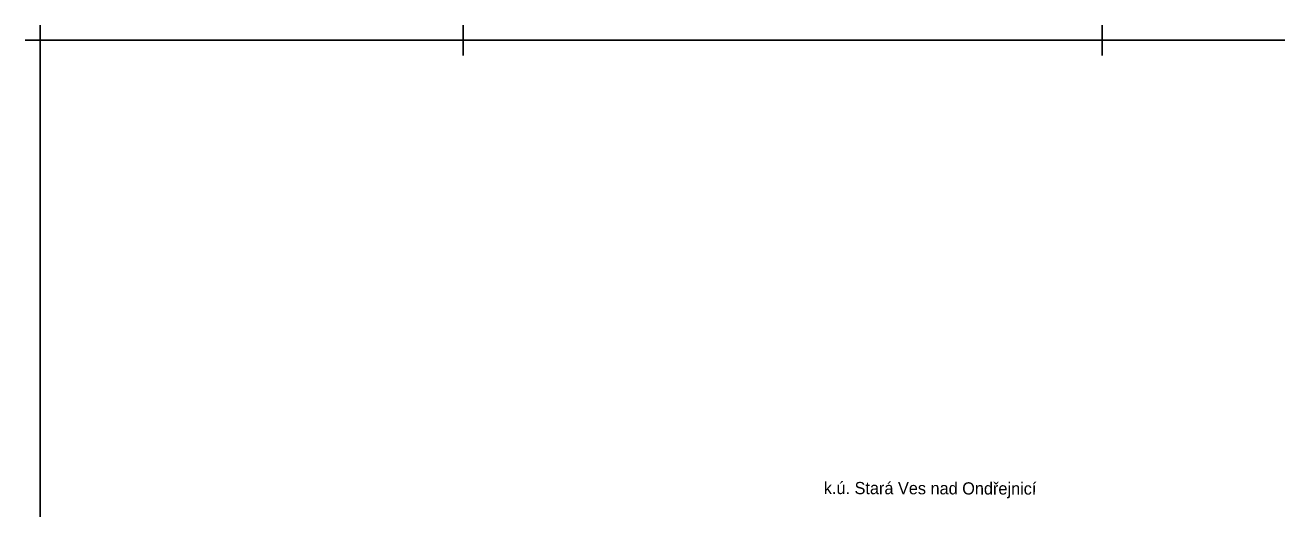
# Model space of a CAD drawing. Extents: x -478645 to -472650, y -1118147 to -1113892.
# Drawn here: x -478645 to -476588, y -1114688 to -1113892 of the extents above; entities that cross this region are included whole.
import ezdxf

# ---------------------------------------------------------------- set-up
doc = ezdxf.new("R2010")
doc.units = 0
for name, color, linetype in [('Implicitní', 7, 'Continuous'), ('okolní k_ú_', 7, 'Continuous'), ('Z_razitko', 7, 'Continuous')]:
    doc.layers.add(name, color=color, linetype=linetype)

msp = doc.modelspace()

# ---------------------------------------------------------------- linework, layer by layer
at = {"layer": 'Implicitní'}
for p, q in [((-478620.405, -1113891.842), (-478620.405, -1113941.842)), ((-478620.405, -1113891.842), (-478620.405, -1113941.842)), ((-478620.405, -1113891.842), (-478620.405, -1113941.842)), ((-478620.405, -1113891.842), (-478620.405, -1113941.842)), ((-478620.405, -1113891.842), (-478620.405, -1113941.842)), ((-478620.405, -1113891.842), (-478620.405, -1113941.842)), ((-478620.405, -1113891.842), (-478620.405, -1113941.842)), ((-478620.405, -1113891.842), (-478620.405, -1113941.842)), ((-478620.405, -1113891.842), (-478620.405, -1113941.842)), ((-478620.405, -1113891.842), (-478620.405, -1113941.842)), ((-478620.405, -1113891.842), (-478620.405, -1113941.842)), ((-478620.405, -1113891.842), (-478620.405, -1113941.842)), ((-478620.405, -1113891.842), (-478620.405, -1113941.842)), ((-478620.405, -1113891.842), (-478620.405, -1113941.842)), ((-478620.405, -1113891.842), (-478620.405, -1113941.842)), ((-478620.405, -1113891.842), (-478620.405, -1113941.842)), ((-478620.405, -1113891.842), (-478620.405, -1113941.842)), ((-478620.405, -1113891.842), (-478620.405, -1113941.842)), ((-478620.405, -1113891.842), (-478620.405, -1113941.842)), ((-478620.405, -1113891.842), (-478620.405, -1113941.842)), ((-478620.405, -1113891.842), (-478620.405, -1113941.842)), ((-478620.405, -1113891.842), (-478620.405, -1113941.842)), ((-478620.405, -1113891.842), (-478620.405, -1113941.842)), ((-478620.405, -1113891.842), (-478620.405, -1113941.842)), ((-478620.405, -1113891.842), (-478620.405, -1113941.842)), ((-478620.405, -1113891.842), (-478620.405, -1113941.842)), ((-478620.405, -1113891.842), (-478620.405, -1113941.842)), ((-478620.405, -1113891.842), (-478620.405, -1113941.842)), ((-478620.405, -1113891.842), (-478620.405, -1113941.842)), ((-478620.405, -1113891.842), (-478620.405, -1113941.842)), ((-478620.405, -1113891.842), (-478620.405, -1113941.842)), ((-477925.486, -1113891.842), (-477925.486, -1113941.842)), ((-477925.486, -1113891.842), (-477925.486, -1113941.842)), ((-477925.486, -1113891.842), (-477925.486, -1113941.842)), ((-477925.486, -1113891.842), (-477925.486, -1113941.842)), ((-477925.486, -1113891.842), (-477925.486, -1113941.842)), ((-477925.486, -1113891.842), (-477925.486, -1113941.842)), ((-477925.486, -1113891.842), (-477925.486, -1113941.842)), ((-477925.486, -1113891.842), (-477925.486, -1113941.842)), ((-477925.486, -1113891.842), (-477925.486, -1113941.842)), ((-477925.486, -1113891.842), (-477925.486, -1113941.842)), ((-477925.486, -1113891.842), (-477925.486, -1113941.842)), ((-477925.486, -1113891.842), (-477925.486, -1113941.842)), ((-477925.486, -1113891.842), (-477925.486, -1113941.842)), ((-477925.486, -1113891.842), (-477925.486, -1113941.842)), ((-477925.486, -1113891.842), (-477925.486, -1113941.842)), ((-477925.486, -1113891.842), (-477925.486, -1113941.842)), ((-477925.486, -1113891.842), (-477925.486, -1113941.842)), ((-477925.486, -1113891.842), (-477925.486, -1113941.842)), ((-477925.486, -1113891.842), (-477925.486, -1113941.842)), ((-477925.486, -1113891.842), (-477925.486, -1113941.842)), ((-477925.486, -1113891.842), (-477925.486, -1113941.842)), ((-477925.486, -1113891.842), (-477925.486, -1113941.842)), ((-477925.486, -1113891.842), (-477925.486, -1113941.842)), ((-477925.486, -1113891.842), (-477925.486, -1113941.842)), ((-477925.486, -1113891.842), (-477925.486, -1113941.842)), ((-477925.486, -1113891.842), (-477925.486, -1113941.842)), ((-477925.486, -1113891.842), (-477925.486, -1113941.842)), ((-477925.486, -1113891.842), (-477925.486, -1113941.842)), ((-477925.486, -1113891.842), (-477925.486, -1113941.842)), ((-477925.486, -1113891.842), (-477925.486, -1113941.842)), ((-477925.486, -1113891.842), (-477925.486, -1113941.842)), ((-476875.486, -1113891.842), (-476875.486, -1113941.842)), ((-476875.486, -1113891.842), (-476875.486, -1113941.842)), ((-476875.486, -1113891.842), (-476875.486, -1113941.842)), ((-476875.486, -1113891.842), (-476875.486, -1113941.842)), ((-476875.486, -1113891.842), (-476875.486, -1113941.842)), ((-476875.486, -1113891.842), (-476875.486, -1113941.842)), ((-476875.486, -1113891.842), (-476875.486, -1113941.842)), ((-476875.486, -1113891.842), (-476875.486, -1113941.842)), ((-476875.486, -1113891.842), (-476875.486, -1113941.842)), ((-476875.486, -1113891.842), (-476875.486, -1113941.842)), ((-476875.486, -1113891.842), (-476875.486, -1113941.842)), ((-476875.486, -1113891.842), (-476875.486, -1113941.842)), ((-476875.486, -1113891.842), (-476875.486, -1113941.842)), ((-476875.486, -1113891.842), (-476875.486, -1113941.842)), ((-476875.486, -1113891.842), (-476875.486, -1113941.842)), ((-476875.486, -1113891.842), (-476875.486, -1113941.842)), ((-476875.486, -1113891.842), (-476875.486, -1113941.842)), ((-476875.486, -1113891.842), (-476875.486, -1113941.842)), ((-476875.486, -1113891.842), (-476875.486, -1113941.842)), ((-476875.486, -1113891.842), (-476875.486, -1113941.842)), ((-476875.486, -1113891.842), (-476875.486, -1113941.842)), ((-476875.486, -1113891.842), (-476875.486, -1113941.842)), ((-476875.486, -1113891.842), (-476875.486, -1113941.842)), ((-476875.486, -1113891.842), (-476875.486, -1113941.842)), ((-476875.486, -1113891.842), (-476875.486, -1113941.842)), ((-476875.486, -1113891.842), (-476875.486, -1113941.842)), ((-476875.486, -1113891.842), (-476875.486, -1113941.842)), ((-476875.486, -1113891.842), (-476875.486, -1113941.842)), ((-476875.486, -1113891.842), (-476875.486, -1113941.842)), ((-476875.486, -1113891.842), (-476875.486, -1113941.842)), ((-476875.486, -1113891.842), (-476875.486, -1113941.842)), ((-476875.405, -1113891.842), (-476875.405, -1113941.842)), ((-476875.405, -1113891.842), (-476875.405, -1113941.842)), ((-476875.405, -1113891.842), (-476875.405, -1113941.842)), ((-476875.405, -1113891.842), (-476875.405, -1113941.842)), ((-476875.405, -1113891.842), (-476875.405, -1113941.842)), ((-476875.405, -1113891.842), (-476875.405, -1113941.842)), ((-476875.405, -1113891.842), (-476875.405, -1113941.842)), ((-476875.405, -1113891.842), (-476875.405, -1113941.842)), ((-476875.405, -1113891.842), (-476875.405, -1113941.842)), ((-476875.405, -1113891.842), (-476875.405, -1113941.842)), ((-476875.405, -1113891.842), (-476875.405, -1113941.842)), ((-476875.405, -1113891.842), (-476875.405, -1113941.842)), ((-476875.405, -1113891.842), (-476875.405, -1113941.842)), ((-476875.405, -1113891.842), (-476875.405, -1113941.842)), ((-476875.405, -1113891.842), (-476875.405, -1113941.842)), ((-476875.405, -1113891.842), (-476875.405, -1113941.842)), ((-476875.405, -1113891.842), (-476875.405, -1113941.842)), ((-476875.405, -1113891.842), (-476875.405, -1113941.842)), ((-476875.405, -1113891.842), (-476875.405, -1113941.842)), ((-476875.405, -1113891.842), (-476875.405, -1113941.842)), ((-476875.405, -1113891.842), (-476875.405, -1113941.842)), ((-476875.405, -1113891.842), (-476875.405, -1113941.842)), ((-476875.405, -1113891.842), (-476875.405, -1113941.842)), ((-476875.405, -1113891.842), (-476875.405, -1113941.842)), ((-476875.405, -1113891.842), (-476875.405, -1113941.842)), ((-476875.405, -1113891.842), (-476875.405, -1113941.842)), ((-476875.405, -1113891.842), (-476875.405, -1113941.842)), ((-476875.405, -1113891.842), (-476875.405, -1113941.842)), ((-476875.405, -1113891.842), (-476875.405, -1113941.842)), ((-476875.405, -1113891.842), (-476875.405, -1113941.842)), ((-476875.405, -1113891.842), (-476875.405, -1113941.842)), ((-478595.405, -1113916.842), (-478645.405, -1113916.842)), ((-478595.405, -1113916.842), (-478645.405, -1113916.842)), ((-478595.405, -1113916.842), (-478645.405, -1113916.842)), ((-478595.405, -1113916.842), (-478645.405, -1113916.842)), ((-478595.405, -1113916.842), (-478645.405, -1113916.842)), ((-478595.405, -1113916.842), (-478645.405, -1113916.842)), ((-478595.405, -1113916.842), (-478645.405, -1113916.842)), ((-478595.405, -1113916.842), (-478645.405, -1113916.842)), ((-478595.405, -1113916.842), (-478645.405, -1113916.842)), ((-478595.405, -1113916.842), (-478645.405, -1113916.842)), ((-478595.405, -1113916.842), (-478645.405, -1113916.842)), ((-478595.405, -1113916.842), (-478645.405, -1113916.842)), ((-478595.405, -1113916.842), (-478645.405, -1113916.842)), ((-478595.405, -1113916.842), (-478645.405, -1113916.842)), ((-478595.405, -1113916.842), (-478645.405, -1113916.842)), ((-478595.405, -1113916.842), (-478645.405, -1113916.842)), ((-478595.405, -1113916.842), (-478645.405, -1113916.842)), ((-478595.405, -1113916.842), (-478645.405, -1113916.842)), ((-478595.405, -1113916.842), (-478645.405, -1113916.842)), ((-478595.405, -1113916.842), (-478645.405, -1113916.842)), ((-478595.405, -1113916.842), (-478645.405, -1113916.842)), ((-478595.405, -1113916.842), (-478645.405, -1113916.842)), ((-478595.405, -1113916.842), (-478645.405, -1113916.842)), ((-478595.405, -1113916.842), (-478645.405, -1113916.842)), ((-478595.405, -1113916.842), (-478645.405, -1113916.842)), ((-478595.405, -1113916.842), (-478645.405, -1113916.842)), ((-478595.405, -1113916.842), (-478645.405, -1113916.842)), ((-478595.405, -1113916.842), (-478645.405, -1113916.842)), ((-478595.405, -1113916.842), (-478645.405, -1113916.842)), ((-478595.405, -1113916.842), (-478645.405, -1113916.842)), ((-478595.405, -1113916.842), (-478645.405, -1113916.842)), ((-477900.486, -1113916.842), (-477950.486, -1113916.842)), ((-477900.486, -1113916.842), (-477950.486, -1113916.842)), ((-477900.486, -1113916.842), (-477950.486, -1113916.842)), ((-477900.486, -1113916.842), (-477950.486, -1113916.842)), ((-477900.486, -1113916.842), (-477950.486, -1113916.842)), ((-477900.486, -1113916.842), (-477950.486, -1113916.842)), ((-477900.486, -1113916.842), (-477950.486, -1113916.842)), ((-477900.486, -1113916.842), (-477950.486, -1113916.842)), ((-477900.486, -1113916.842), (-477950.486, -1113916.842)), ((-477900.486, -1113916.842), (-477950.486, -1113916.842)), ((-477900.486, -1113916.842), (-477950.486, -1113916.842)), ((-477900.486, -1113916.842), (-477950.486, -1113916.842)), ((-477900.486, -1113916.842), (-477950.486, -1113916.842)), ((-477900.486, -1113916.842), (-477950.486, -1113916.842)), ((-477900.486, -1113916.842), (-477950.486, -1113916.842)), ((-477900.486, -1113916.842), (-477950.486, -1113916.842)), ((-477900.486, -1113916.842), (-477950.486, -1113916.842)), ((-477900.486, -1113916.842), (-477950.486, -1113916.842)), ((-477900.486, -1113916.842), (-477950.486, -1113916.842)), ((-477900.486, -1113916.842), (-477950.486, -1113916.842)), ((-477900.486, -1113916.842), (-477950.486, -1113916.842)), ((-477900.486, -1113916.842), (-477950.486, -1113916.842)), ((-477900.486, -1113916.842), (-477950.486, -1113916.842)), ((-477900.486, -1113916.842), (-477950.486, -1113916.842)), ((-477900.486, -1113916.842), (-477950.486, -1113916.842)), ((-477900.486, -1113916.842), (-477950.486, -1113916.842)), ((-477900.486, -1113916.842), (-477950.486, -1113916.842)), ((-477900.486, -1113916.842), (-477950.486, -1113916.842)), ((-477900.486, -1113916.842), (-477950.486, -1113916.842)), ((-477900.486, -1113916.842), (-477950.486, -1113916.842)), ((-477900.486, -1113916.842), (-477950.486, -1113916.842)), ((-476850.486, -1113916.842), (-476900.486, -1113916.842)), ((-476850.486, -1113916.842), (-476900.486, -1113916.842)), ((-476850.486, -1113916.842), (-476900.486, -1113916.842)), ((-476850.486, -1113916.842), (-476900.486, -1113916.842)), ((-476850.486, -1113916.842), (-476900.486, -1113916.842)), ((-476850.486, -1113916.842), (-476900.486, -1113916.842)), ((-476850.486, -1113916.842), (-476900.486, -1113916.842)), ((-476850.486, -1113916.842), (-476900.486, -1113916.842)), ((-476850.486, -1113916.842), (-476900.486, -1113916.842)), ((-476850.486, -1113916.842), (-476900.486, -1113916.842)), ((-476850.486, -1113916.842), (-476900.486, -1113916.842)), ((-476850.486, -1113916.842), (-476900.486, -1113916.842)), ((-476850.486, -1113916.842), (-476900.486, -1113916.842)), ((-476850.486, -1113916.842), (-476900.486, -1113916.842)), ((-476850.486, -1113916.842), (-476900.486, -1113916.842)), ((-476850.486, -1113916.842), (-476900.486, -1113916.842)), ((-476850.486, -1113916.842), (-476900.486, -1113916.842)), ((-476850.486, -1113916.842), (-476900.486, -1113916.842)), ((-476850.486, -1113916.842), (-476900.486, -1113916.842)), ((-476850.486, -1113916.842), (-476900.486, -1113916.842)), ((-476850.486, -1113916.842), (-476900.486, -1113916.842)), ((-476850.486, -1113916.842), (-476900.486, -1113916.842)), ((-476850.486, -1113916.842), (-476900.486, -1113916.842)), ((-476850.486, -1113916.842), (-476900.486, -1113916.842)), ((-476850.486, -1113916.842), (-476900.486, -1113916.842)), ((-476850.486, -1113916.842), (-476900.486, -1113916.842)), ((-476850.486, -1113916.842), (-476900.486, -1113916.842)), ((-476850.486, -1113916.842), (-476900.486, -1113916.842)), ((-476850.486, -1113916.842), (-476900.486, -1113916.842)), ((-476850.486, -1113916.842), (-476900.486, -1113916.842)), ((-476850.486, -1113916.842), (-476900.486, -1113916.842)), ((-476850.405, -1113916.842), (-476900.405, -1113916.842)), ((-476850.405, -1113916.842), (-476900.405, -1113916.842)), ((-476850.405, -1113916.842), (-476900.405, -1113916.842)), ((-476850.405, -1113916.842), (-476900.405, -1113916.842)), ((-476850.405, -1113916.842), (-476900.405, -1113916.842)), ((-476850.405, -1113916.842), (-476900.405, -1113916.842)), ((-476850.405, -1113916.842), (-476900.405, -1113916.842)), ((-476850.405, -1113916.842), (-476900.405, -1113916.842)), ((-476850.405, -1113916.842), (-476900.405, -1113916.842)), ((-476850.405, -1113916.842), (-476900.405, -1113916.842)), ((-476850.405, -1113916.842), (-476900.405, -1113916.842)), ((-476850.405, -1113916.842), (-476900.405, -1113916.842)), ((-476850.405, -1113916.842), (-476900.405, -1113916.842)), ((-476850.405, -1113916.842), (-476900.405, -1113916.842)), ((-476850.405, -1113916.842), (-476900.405, -1113916.842)), ((-476850.405, -1113916.842), (-476900.405, -1113916.842)), ((-476850.405, -1113916.842), (-476900.405, -1113916.842)), ((-476850.405, -1113916.842), (-476900.405, -1113916.842)), ((-476850.405, -1113916.842), (-476900.405, -1113916.842)), ((-476850.405, -1113916.842), (-476900.405, -1113916.842)), ((-476850.405, -1113916.842), (-476900.405, -1113916.842)), ((-476850.405, -1113916.842), (-476900.405, -1113916.842)), ((-476850.405, -1113916.842), (-476900.405, -1113916.842)), ((-476850.405, -1113916.842), (-476900.405, -1113916.842)), ((-476850.405, -1113916.842), (-476900.405, -1113916.842)), ((-476850.405, -1113916.842), (-476900.405, -1113916.842)), ((-476850.405, -1113916.842), (-476900.405, -1113916.842)), ((-476850.405, -1113916.842), (-476900.405, -1113916.842)), ((-476850.405, -1113916.842), (-476900.405, -1113916.842)), ((-476850.405, -1113916.842), (-476900.405, -1113916.842)), ((-476850.405, -1113916.842), (-476900.405, -1113916.842))]:
    msp.add_line(p, q, dxfattribs=at)
at = {"layer": 'Z_razitko'}
msp.add_lwpolyline([(-478620.405, -1118121.842), (-472675.405, -1118121.842), (-472675.405, -1113916.842), (-478620.405, -1113916.842)], close=True, dxfattribs=at)

# ---------------------------------------------------------------- texts
at = {"layer": 'okolní k_ú_'}
msp.add_text('k.ú. Stará Ves nad Ondřejnicí', height=20, rotation=359.823686, dxfattribs=at).set_placement((-477332.764, -1114663.273))

doc.saveas('drawing.dxf')
